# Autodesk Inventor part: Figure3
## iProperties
Shininess: 77.0
Length Units: 11269
Angle Units: 11279
Time Units: 11290
Mass Units: 11283
Length Display Precision: 3
Angle Display Precision: 2
Created: 2001-12
Part Number: Figure3
Document SubType Name: Modeling
Designer: CADSoft
Density: 0.0
Volumn: 0.0
Area: 0.0
PropertySet Name: Model Information
Control State: 0
Master: False
Checked Out: False
Author: CADSoft
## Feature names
1. Extrusion2
